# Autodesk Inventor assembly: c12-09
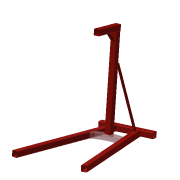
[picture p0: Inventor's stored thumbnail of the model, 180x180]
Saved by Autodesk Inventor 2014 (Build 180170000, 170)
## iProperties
Created: 2011-01
Part Number: c12-09
Document SubType Name: Assembly
Designer: Thom Tremblay
_SolveAssemblyDoc: Frame Generator Solve Assembly
_Version: 15.0.0
Author: Thom Tremblay
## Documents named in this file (3)
- C:\Inventor 2014 Essentials\Assemblies\Chapter 12\c12-09.iam
- C:\Inventor 2014 Essentials\Assemblies\Chapter 12\Frame\Frame c12-09.iam
- C:\Inventor 2014 Essentials\Parts\Chapter 12\c12-02.ipt
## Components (2 placed, 2 different names)
1. c12-02:1
2. Frame c12-09:1 [sub-assembly]
